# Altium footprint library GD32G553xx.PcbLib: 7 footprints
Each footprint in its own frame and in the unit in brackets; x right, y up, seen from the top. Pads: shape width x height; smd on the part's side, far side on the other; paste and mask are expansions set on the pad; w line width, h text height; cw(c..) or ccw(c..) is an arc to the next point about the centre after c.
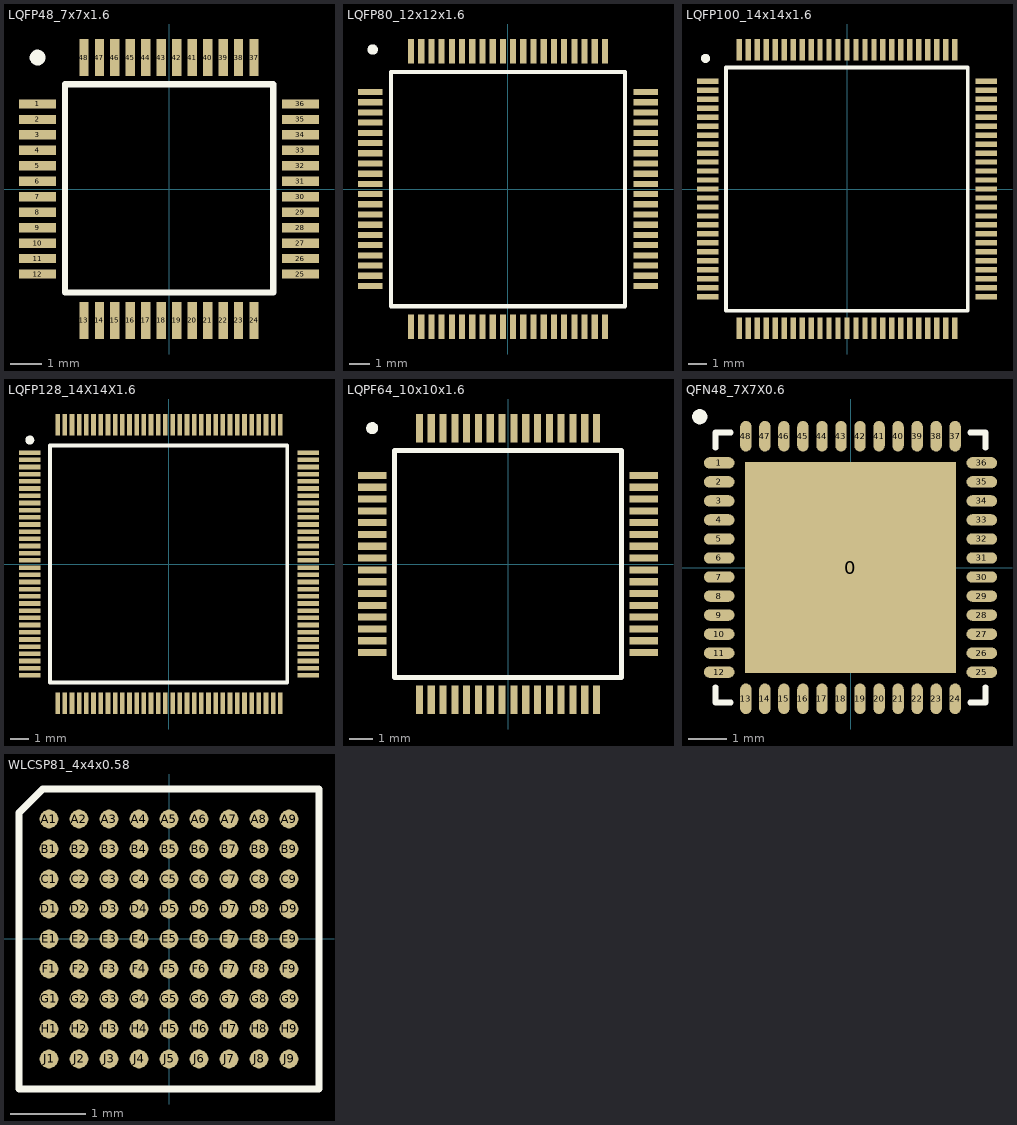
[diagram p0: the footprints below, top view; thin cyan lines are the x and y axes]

## LQFP48_7x7x1.6 [mm]
pads (48):
  rect 1.2x0.3 smd: 1(-4.25,2.75) 2(-4.25,2.25) 3(-4.25,1.75) 4(-4.25,1.25) 5(-4.25,0.75) 6(-4.25,0.25) 7(-4.25,-0.25) 8(-4.25,-0.75) 9(-4.25,-1.25) 10(-4.25,-1.75) 11(-4.25,-2.25) 12(-4.25,-2.75) 25(4.25,-2.75) 26(4.25,-2.25) 27(4.25,-1.75) 28(4.25,-1.25) 29(4.25,-0.75) 30(4.25,-0.25) 31(4.25,0.25) 32(4.25,0.75) 33(4.25,1.25) 34(4.25,1.75) 35(4.25,2.25) 36(4.25,2.75)
  rect 0.3x1.2 smd: 13(-2.75,-4.25) 14(-2.25,-4.25) 15(-1.75,-4.25) 16(-1.25,-4.25) 17(-0.75,-4.25) 18(-0.25,-4.25) 19(0.25,-4.25) 20(0.75,-4.25) 21(1.25,-4.25) 22(1.75,-4.25) 23(2.25,-4.25) 24(2.75,-4.25) 37(2.75,4.25) 38(2.25,4.25) 39(1.75,4.25) 40(1.25,4.25) 41(0.75,4.25) 42(0.25,4.25) 43(-0.25,4.25) 44(-0.75,4.25) 45(-1.25,4.25) 46(-1.75,4.25) 47(-2.25,4.25) 48(-2.75,4.25)
Top Overlay:
  circle w0.254: c-4.25,4.25 r0.127
  lines w0.203: -3.361,-3.346 3.37,-3.346 3.37,3.385 -3.361,3.385 -3.361,-3.346
3D body "TSQFP50P900X900X160-48N.step": height 1.6, standoff 0, extent -4.5,-4.5 4.5,4.5

## LQFP80_12x12x1.6 [mm]
pads (80):
  rect 1.2x0.3 smd: 1(-6.75,4.75) 2(-6.75,4.25) 3(-6.75,3.75) 4(-6.75,3.25) 5(-6.75,2.75) 6(-6.75,2.25) 7(-6.75,1.75) 8(-6.75,1.25) 9(-6.75,0.75) 10(-6.75,0.25) 11(-6.75,-0.25) 12(-6.75,-0.75) 13(-6.75,-1.25) 14(-6.75,-1.75) 15(-6.75,-2.25) 16(-6.75,-2.75) 17(-6.75,-3.25) 18(-6.75,-3.75) 19(-6.75,-4.25) 20(-6.75,-4.75) 41(6.75,-4.75) 42(6.75,-4.25) 43(6.75,-3.75) 44(6.75,-3.25) 45(6.75,-2.75) 46(6.75,-2.25) 47(6.75,-1.75) 48(6.75,-1.25) 49(6.75,-0.75) 50(6.75,-0.25) 51(6.75,0.25) 52(6.75,0.75) 53(6.75,1.25) 54(6.75,1.75) 55(6.75,2.25) 56(6.75,2.75) 57(6.75,3.25) 58(6.75,3.75) 59(6.75,4.25) 60(6.75,4.75)
  rect 0.3x1.2 smd: 21(-4.75,-6.75) 22(-4.25,-6.75) 23(-3.75,-6.75) 24(-3.25,-6.75) 25(-2.75,-6.75) 26(-2.25,-6.75) 27(-1.75,-6.75) 28(-1.25,-6.75) 29(-0.75,-6.75) 30(-0.25,-6.75) 31(0.25,-6.75) 32(0.75,-6.75) 33(1.25,-6.75) 34(1.75,-6.75) 35(2.25,-6.75) 36(2.75,-6.75) 37(3.25,-6.75) 38(3.75,-6.75) 39(4.25,-6.75) 40(4.75,-6.75) 61(4.75,6.75) 62(4.25,6.75) 63(3.75,6.75) 64(3.25,6.75) 65(2.75,6.75) 66(2.25,6.75) 67(1.75,6.75) 68(1.25,6.75) 69(0.75,6.75) 70(0.25,6.75) 71(-0.25,6.75) 72(-0.75,6.75) 73(-1.25,6.75) 74(-1.75,6.75) 75(-2.25,6.75) 76(-2.75,6.75) 77(-3.25,6.75) 78(-3.75,6.75) 79(-4.25,6.75) 80(-4.75,6.75)
Top Overlay:
  circle w0.254: c-6.629,6.833 r0.127
  lines w0.203: -5.734,-5.746 -5.734,5.735 5.724,5.735 5.724,-5.746 -5.734,-5.746
3D body "TSQFP50P1400X1400X160-80N.step": height 1.6, standoff 0, extent -7,-7 7,7

## LQFP100_14x14x1.6 [mm]
pads (100):
  rect 1.2x0.3 smd: 1(-7.75,6) 2(-7.75,5.5) 3(-7.75,5) 4(-7.75,4.5) 5(-7.75,4) 6(-7.75,3.5) 7(-7.75,3) 8(-7.75,2.5) 9(-7.75,2) 10(-7.75,1.5) 11(-7.75,1) 12(-7.75,0.5) 13(-7.75,0) 14(-7.75,-0.5) 15(-7.75,-1) 16(-7.75,-1.5) 17(-7.75,-2) 18(-7.75,-2.5) 19(-7.75,-3) 20(-7.75,-3.5) 21(-7.75,-4) 22(-7.75,-4.5) 23(-7.75,-5) 24(-7.75,-5.5) 25(-7.75,-6) 51(7.75,-6) 52(7.75,-5.5) 53(7.75,-5) 54(7.75,-4.5) 55(7.75,-4) 56(7.75,-3.5) 57(7.75,-3) 58(7.75,-2.5) 59(7.75,-2) 60(7.75,-1.5) 61(7.75,-1) 62(7.75,-0.5) 63(7.75,0) 64(7.75,0.5) 65(7.75,1) 66(7.75,1.5) 67(7.75,2) 68(7.75,2.5) 69(7.75,3) 70(7.75,3.5) 71(7.75,4) 72(7.75,4.5) 73(7.75,5) 74(7.75,5.5) 75(7.75,6)
  rect 0.3x1.2 smd: 26(-6,-7.75) 27(-5.5,-7.75) 28(-5,-7.75) 29(-4.5,-7.75) 30(-4,-7.75) 31(-3.5,-7.75) 32(-3,-7.75) 33(-2.5,-7.75) 34(-2,-7.75) 35(-1.5,-7.75) 36(-1,-7.75) 37(-0.5,-7.75) 38(0,-7.75) 39(0.5,-7.75) 40(1,-7.75) 41(1.5,-7.75) 42(2,-7.75) 43(2.5,-7.75) 44(3,-7.75) 45(3.5,-7.75) 46(4,-7.75) 47(4.5,-7.75) 48(5,-7.75) 49(5.5,-7.75) 50(6,-7.75) 76(6,7.75) 77(5.5,7.75) 78(5,7.75) 79(4.5,7.75) 80(4,7.75) 81(3.5,7.75) 82(3,7.75) 83(2.5,7.75) 84(2,7.75) 85(1.5,7.75) 86(1,7.75) 87(0.5,7.75) 88(0,7.75) 89(-0.5,7.75) 90(-1,7.75) 91(-1.5,7.75) 92(-2,7.75) 93(-2.5,7.75) 94(-3,7.75) 95(-3.5,7.75) 96(-4,7.75) 97(-4.5,7.75) 98(-5,7.75) 99(-5.5,7.75) 100(-6,7.75)
Top Overlay:
  circle w0.254: c-7.877,7.27 r0.127
  lines w0.203: -6.734,-6.782 -6.734,6.762 6.728,6.762 6.728,-6.782 -6.734,-6.782
3D body "TSQFP50P1600X1600X160-100N.step": height 1.6, standoff 0, extent -8,-8 8,8

## LQFP128_14X14X1.6 [mm]
height 1.6
pads (128):
  rect 1.2x0.26 smd: 1(-7.725,6.2) 2(-7.725,5.8) 3(-7.725,5.4) 4(-7.725,5) 5(-7.725,4.6) 6(-7.725,4.2) 7(-7.725,3.8) 8(-7.725,3.4) 9(-7.725,3) 10(-7.725,2.6) 11(-7.725,2.2) 12(-7.725,1.8) 13(-7.725,1.4) 14(-7.725,1) 15(-7.725,0.6) 16(-7.725,0.2) 17(-7.725,-0.2) 18(-7.725,-0.6) 19(-7.725,-1) 20(-7.725,-1.4) 21(-7.725,-1.8) 22(-7.725,-2.2) 23(-7.725,-2.6) 24(-7.725,-3) 25(-7.725,-3.4) 26(-7.725,-3.8) 27(-7.725,-4.2) 28(-7.725,-4.6) 29(-7.725,-5) 30(-7.725,-5.4) 31(-7.725,-5.8) 32(-7.725,-6.2) 65(7.775,-6.2) 66(7.775,-5.8) 67(7.775,-5.4) 68(7.775,-5) 69(7.775,-4.6) 70(7.775,-4.2) 71(7.775,-3.8) 72(7.775,-3.4) 73(7.775,-3) 74(7.775,-2.6) 75(7.775,-2.2) 76(7.775,-1.8) 77(7.775,-1.4) 78(7.775,-1) 79(7.775,-0.6) 80(7.775,-0.2) 81(7.775,0.2) 82(7.775,0.6) 83(7.775,1) 84(7.775,1.4) 85(7.775,1.8) 86(7.775,2.2) 87(7.775,2.6) 88(7.775,3) 89(7.775,3.4) 90(7.775,3.8) 91(7.775,4.2) 92(7.775,4.6) 93(7.775,5) 94(7.775,5.4) 95(7.775,5.8) 96(7.775,6.2)
  rect 0.26x1.2 smd: 33(-6.175,-7.75) 34(-5.775,-7.75) 35(-5.375,-7.75) 36(-4.975,-7.75) 37(-4.575,-7.75) 38(-4.175,-7.75) 39(-3.775,-7.75) 40(-3.375,-7.75) 41(-2.975,-7.75) 42(-2.575,-7.75) 43(-2.175,-7.75) 44(-1.775,-7.75) 45(-1.375,-7.75) 46(-0.975,-7.75) 47(-0.575,-7.75) 48(-0.175,-7.75) 49(0.225,-7.75) 50(0.625,-7.75) 51(1.025,-7.75) 52(1.425,-7.75) 53(1.825,-7.75) 54(2.225,-7.75) 55(2.625,-7.75) 56(3.025,-7.75) 57(3.425,-7.75) 58(3.825,-7.75) 59(4.225,-7.75) 60(4.625,-7.75) 61(5.025,-7.75) 62(5.425,-7.75) 63(5.825,-7.75) 64(6.225,-7.75) 97(6.225,7.75) 98(5.825,7.75) 99(5.425,7.75) 100(5.025,7.75) 101(4.625,7.75) 102(4.225,7.75) 103(3.825,7.75) 104(3.425,7.75) 105(3.025,7.75) 106(2.625,7.75) 107(2.225,7.75) 108(1.825,7.75) 109(1.425,7.75) 110(1.025,7.75) 111(0.625,7.75) 112(0.225,7.75) 113(-0.175,7.75) 114(-0.575,7.75) 115(-0.975,7.75) 116(-1.375,7.75) 117(-1.775,7.75) 118(-2.175,7.75) 119(-2.575,7.75) 120(-2.975,7.75) 121(-3.375,7.75) 122(-3.775,7.75) 123(-4.175,7.75) 124(-4.575,7.75) 125(-4.975,7.75) 126(-5.375,7.75) 127(-5.775,7.75) 128(-6.175,7.75)
Top Overlay:
  circle w0.25: c-7.725,6.9 r0.125
  lines w0.203: -6.6,-6.6 -6.6,6.6 6.6,6.6 6.6,-6.6 -6.6,-6.6
3D body "TSQFP40P1600X1600X160-128N.step": height 1.6, standoff 0, extent -7.975,-7.999 8.025,8.001

## LQPF64_10x10x1.6 [mm]
pads (64):
  rect 1.2x0.3 smd: 1(-5.75,3.75) 2(-5.75,3.25) 3(-5.75,2.75) 4(-5.75,2.25) 5(-5.75,1.75) 6(-5.75,1.25) 7(-5.75,0.75) 8(-5.75,0.25) 9(-5.75,-0.25) 10(-5.75,-0.75) 11(-5.75,-1.25) 12(-5.75,-1.75) 13(-5.75,-2.25) 14(-5.75,-2.75) 15(-5.75,-3.25) 16(-5.75,-3.75) 33(5.75,-3.75) 34(5.75,-3.25) 35(5.75,-2.75) 36(5.75,-2.25) 37(5.75,-1.75) 38(5.75,-1.25) 39(5.75,-0.75) 40(5.75,-0.25) 41(5.75,0.25) 42(5.75,0.75) 43(5.75,1.25) 44(5.75,1.75) 45(5.75,2.25) 46(5.75,2.75) 47(5.75,3.25) 48(5.75,3.75)
  rect 0.3x1.2 smd: 17(-3.75,-5.75) 18(-3.25,-5.75) 19(-2.75,-5.75) 20(-2.25,-5.75) 21(-1.75,-5.75) 22(-1.25,-5.75) 23(-0.75,-5.75) 24(-0.25,-5.75) 25(0.25,-5.75) 26(0.75,-5.75) 27(1.25,-5.75) 28(1.75,-5.75) 29(2.25,-5.75) 30(2.75,-5.75) 31(3.25,-5.75) 32(3.75,-5.75) 49(3.75,5.75) 50(3.25,5.75) 51(2.75,5.75) 52(2.25,5.75) 53(1.75,5.75) 54(1.25,5.75) 55(0.75,5.75) 56(0.25,5.75) 57(-0.25,5.75) 58(-0.75,5.75) 59(-1.25,5.75) 60(-1.75,5.75) 61(-2.25,5.75) 62(-2.75,5.75) 63(-3.25,5.75) 64(-3.75,5.75)
Top Overlay:
  circle w0.254: c-5.75,5.75 r0.127
  lines w0.203: -4.801,-4.801 -4.801,4.801 4.801,4.801 4.801,-4.801 -4.801,-4.801
3D body "TSQFP50P1200X1200X160-64N.step": height 1.6, standoff 0, extent -6,-6 6,6

## QFN48_7X7X0.6 [mm]
pads (49):
  rect 5.55x5.55 smd: 0(0,0)
  oval 0.8x0.3 smd: 1(-3.45,2.75) 2(-3.45,2.25) 3(-3.45,1.75) 4(-3.45,1.25) 5(-3.45,0.75) 6(-3.45,0.25) 7(-3.45,-0.25) 8(-3.45,-0.75) 9(-3.45,-1.25) 10(-3.45,-1.75) 11(-3.45,-2.25) 12(-3.45,-2.75) 25(3.45,-2.75) 26(3.45,-2.25) 27(3.45,-1.75) 28(3.45,-1.25) 29(3.45,-0.75) 30(3.45,-0.25) 31(3.45,0.25) 32(3.45,0.75) 33(3.45,1.25) 34(3.45,1.75) 35(3.45,2.25) 36(3.45,2.75)
  oval 0.3x0.8 smd: 13(-2.75,-3.45) 14(-2.25,-3.45) 15(-1.75,-3.45) 16(-1.25,-3.45) 17(-0.75,-3.45) 18(-0.25,-3.45) 19(0.25,-3.45) 20(0.75,-3.45) 21(1.25,-3.45) 22(1.75,-3.45) 23(2.25,-3.45) 24(2.75,-3.45) 37(2.75,3.45) 38(2.25,3.45) 39(1.75,3.45) 40(1.25,3.45) 41(0.75,3.45) 42(0.25,3.45) 43(-0.25,3.45) 44(-0.75,3.45) 45(-1.25,3.45) 46(-1.75,3.45) 47(-2.25,3.45) 48(-2.75,3.45)
Top Overlay:
  circle w0.254: c-3.962,3.962 r0.072
  lines w0.152: -3.551,-3.15 -3.551,-3.551 -3.15,-3.551 ; -3.551,3.15 -3.551,3.551 -3.15,3.551 ; 3.15,-3.551 3.551,-3.551 3.551,-3.15 ; 3.15,3.551 3.551,3.551 3.551,3.15
3D body "QFN50P700X700X60_HS-49N.step": height 0.6, standoff 0, extent -3.576,-3.551 3.526,3.551

## WLCSP81_4x4x0.58 [mm]
pads (81):
  round 0.25 smd mask+0.04: A1(-1.6,1.6) A2(-1.2,1.6) A3(-0.8,1.6) A4(-0.4,1.6) A5(0,1.6) A6(0.4,1.6) A7(0.8,1.6) A8(1.2,1.6) A9(1.6,1.6) B1(-1.6,1.2) B2(-1.2,1.2) B3(-0.8,1.2) B4(-0.4,1.2) B5(0,1.2) B6(0.4,1.2) B7(0.8,1.2) B8(1.2,1.2) B9(1.6,1.2) C1(-1.6,0.8) C2(-1.2,0.8) C3(-0.8,0.8) C4(-0.4,0.8) C5(0,0.8) C6(0.4,0.8) C7(0.8,0.8) C8(1.2,0.8) C9(1.6,0.8) D1(-1.6,0.4) D2(-1.2,0.4) D3(-0.8,0.4) D4(-0.4,0.4) D5(0,0.4) D6(0.4,0.4) D7(0.8,0.4) D8(1.2,0.4) D9(1.6,0.4) E1(-1.6,0) E2(-1.2,0) E3(-0.8,0) E4(-0.4,0) E5(0,0) E6(0.4,0) E7(0.8,0) E8(1.2,0) E9(1.6,0) F1(-1.6,-0.4) F2(-1.2,-0.4) F3(-0.8,-0.4) F4(-0.4,-0.4) F5(0,-0.4) F6(0.4,-0.4) F7(0.8,-0.4) F8(1.2,-0.4) F9(1.6,-0.4) G1(-1.6,-0.8) G2(-1.2,-0.8) G3(-0.8,-0.8) G4(-0.4,-0.8) G5(0,-0.8) G6(0.4,-0.8) G7(0.8,-0.8) G8(1.2,-0.8) G9(1.6,-0.8) H1(-1.6,-1.2) H2(-1.2,-1.2) H3(-0.8,-1.2) H4(-0.4,-1.2) H5(0,-1.2) H6(0.4,-1.2) H7(0.8,-1.2) H8(1.2,-1.2) H9(1.6,-1.2) J1(-1.6,-1.6) J2(-1.2,-1.6) J3(-0.8,-1.6) J4(-0.4,-1.6) J5(0,-1.6) J6(0.4,-1.6) J7(0.8,-1.6) J8(1.2,-1.6) J9(1.6,-1.6)
Top Overlay:
  lines w0.1: -2,-2 2,-2 2,2 -1.683,2 -2,1.683 -2,-2
3D body "BGA81C40P9X9_400X400X58.step": height 0.58, standoff 0, extent -2,-2 2,2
